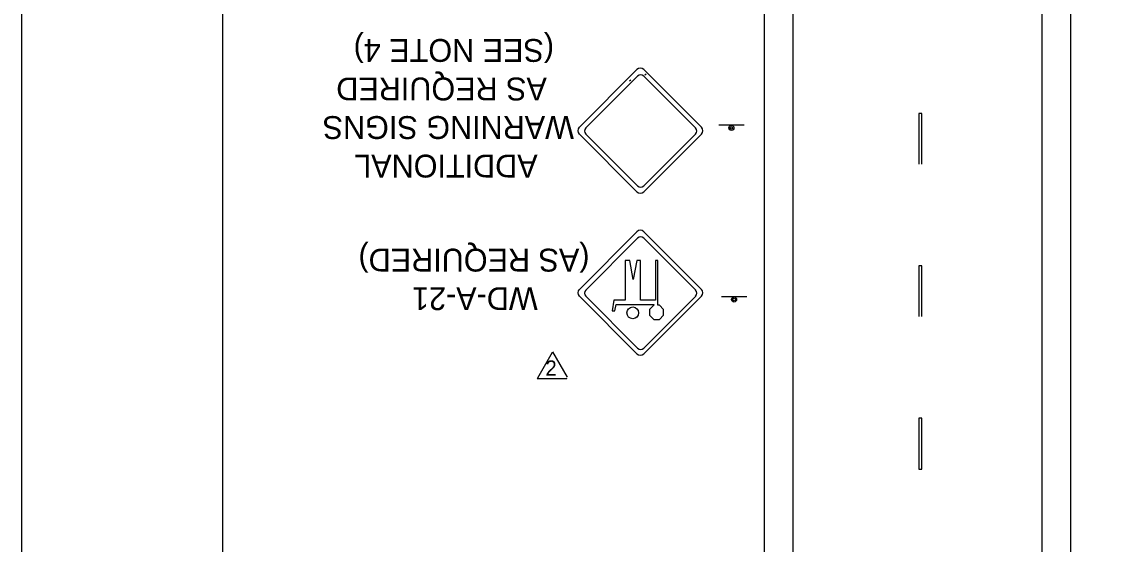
# Model space of a CAD drawing. Extents: x 2195 to 2411, y 202 to 481.
# Drawn here: x 2195.4 to 2299.6, y 363.1 to 412.8 of the extents above; entities that cross this region are included whole.
import ezdxf

# ---------------------------------------------------------------- set-up
doc = ezdxf.new("R2010")
doc.units = 0
for name, color, linetype in [('Level 1', 7, 'Continuous'), ('Level 10', 7, 'Continuous'), ('Level 2', 7, 'Continuous'), ('Level 44', 7, 'Continuous'), ('Level 60', 7, 'Continuous')]:
    doc.layers.add(name, color=color, linetype=linetype)

msp = doc.modelspace()

# ---------------------------------------------------------------- linework, layer by layer
at = {"layer": 'Level 1'}
for p, q in [((2253.3, 390.08), (2252.84, 390.08)), ((2252.84, 390.08), (2252.84, 386.29)), ((2253.62, 388.26), (2253.3, 390.08)), ((2253.96, 390.08), (2253.62, 388.26)), ((2254.33, 390.08), (2253.96, 390.08)), ((2254.33, 386.29), (2254.33, 390.08)), ((2255.95, 390.08), (2255.75, 390.08)), ((2255.75, 390.08), (2255.75, 386.29)), ((2255.95, 385.82), (2255.95, 390.08)), ((2251.77, 386.29), (2251.61, 385.29)), ((2252.84, 386.29), (2251.77, 386.29)), ((2251.86, 385.29), (2252, 385.89)), ((2252, 385.89), (2255.57, 385.89)), ((2255.75, 386.29), (2254.33, 386.29)), ((2255.57, 385.82), (2255.18, 385.42)), ((2255.57, 385.89), (2255.57, 385.82)), ((2256.13, 385.82), (2255.95, 385.82)), ((2256.52, 385.42), (2256.13, 385.82)), ((2251.61, 385.29), (2251.86, 385.29)), ((2255.18, 385.42), (2255.18, 384.86)), ((2255.18, 384.86), (2255.57, 384.47)), ((2256.13, 384.47), (2256.52, 384.86)), ((2256.52, 384.86), (2256.52, 385.42)), ((2255.57, 384.47), (2256.13, 384.47))]:
    msp.add_line(p, q, dxfattribs=at)
msp.add_circle((2253.58, 385.09), 0.559, dxfattribs=at)
at = {"layer": 'Level 10'}
for p, q in [((2266.09, 465.71), (2266.09, 217.7)), ((2268.81, 465.71), (2268.81, 217.7)), ((2292.52, 447.88), (2292.52, 311.49)), ((2295.26, 447.88), (2295.26, 217.7))]:
    msp.add_line(p, q, dxfattribs=at)
at = {"layer": 'Level 2'}
for p, q in [((2254.74, 407.74), (2254.84, 407.84)), ((2253.28, 407.17), (2253.38, 407.27)), ((2280.81, 404.08), (2280.81, 399.24)), ((2281.1, 404.08), (2280.81, 404.08)), ((2281.1, 399.24), (2281.1, 404.08)), ((2280.81, 389.57), (2280.81, 384.73)), ((2281.1, 389.57), (2280.81, 389.57)), ((2281.1, 384.73), (2281.1, 389.57)), ((2280.81, 375.05), (2280.81, 370.21)), ((2281.1, 375.05), (2280.81, 375.05)), ((2281.1, 370.21), (2281.1, 375.05)), ((2280.81, 370.21), (2281.1, 370.21))]:
    msp.add_line(p, q, dxfattribs=at)
at = {"layer": 'Level 44'}
for p, q in [((2253.97, 408.25), (2248.49, 402.75)), ((2249.1, 402.69), (2254.04, 407.63)), ((2260.11, 402.75), (2254.62, 408.25)), ((2254.62, 407.63), (2259.56, 402.69)), ((2260.11, 402.75), (2260.11, 402.75)), ((2264.18, 402.96), (2261.76, 402.96)), ((2248.49, 402.1), (2253.97, 396.62)), ((2254.04, 397.17), (2249.1, 402.11)), ((2259.56, 402.11), (2254.62, 397.17)), ((2254.62, 396.62), (2260.11, 402.1)), ((2253.98, 392.81), (2248.49, 387.32)), ((2249.1, 387.26), (2254.04, 392.2)), ((2260.12, 387.32), (2254.63, 392.81)), ((2254.63, 392.2), (2259.57, 387.26)), ((2248.49, 386.67), (2253.98, 381.19)), ((2254.04, 381.74), (2249.1, 386.68)), ((2259.57, 386.68), (2254.63, 381.74)), ((2254.63, 381.19), (2260.12, 386.67)), ((2260.11, 387.32), (2260.12, 387.32)), ((2264.45, 386.63), (2262.03, 386.63))]:
    msp.add_line(p, q, dxfattribs=at)
for centre, radius in [((2262.97, 402.69), 0.242), ((2262.97, 402.69), 0.121), ((2263.23, 386.36), 0.242), ((2263.23, 386.36), 0.121)]:
    msp.add_circle(centre, radius, dxfattribs=at)
for centre, radius, start, end in [((2254.3, 407.92), 0.459, 45, 135), ((2254.33, 407.34), 0.413, 45, 135), ((2248.81, 402.43), 0.459, 135, 225), ((2249.39, 402.4), 0.413, 135, 225), ((2259.27, 402.4), 0.413, 315, 45), ((2259.79, 402.43), 0.459, 315, 45), ((2254.33, 397.46), 0.413, 225, 315), ((2254.3, 396.94), 0.459, 225, 315), ((2254.3, 392.49), 0.459, 45, 135), ((2254.33, 391.91), 0.413, 45, 135), ((2248.81, 387), 0.459, 135, 225), ((2249.4, 386.97), 0.413, 135, 225), ((2259.27, 386.97), 0.413, 315, 45), ((2259.79, 387), 0.459, 315, 45), ((2254.33, 382.03), 0.413, 225, 315), ((2254.3, 381.51), 0.459, 225, 315)]:
    msp.add_arc(centre, radius, start, end, dxfattribs=at)
at = {"layer": 'Level 60'}
for points in [[(2195.4, 480.88), (2411.4, 480.88), (2411.4, 201.88), (2195.4, 201.88)], [(2214.53, 470.07), (2401.4, 470.07), (2401.4, 212.69), (2214.53, 212.69)]]:
    msp.add_lwpolyline(points, close=True, dxfattribs=at)
for points in [[(2245.89, 381.31), (2244.5, 378.88)], [(2247.37, 378.96), (2245.98, 381.38)], [(2244.5, 378.88), (2244.47, 378.84), (2247.31, 378.84), (2247.29, 378.88)]]:
    msp.add_lwpolyline(points, dxfattribs=at)

# ---------------------------------------------------------------- texts
at = {"layer": 'Level 10'}
for s, height, p in [('(SEE NOTE 4)', 2.177, (2246.08, 411.16)), ('AS REQUIRED', 2.177, (2245.4, 407.49)), ('WARNING SIGNS ', 2.177, (2247.98, 403.82)), ('ADDITIONAL ', 2.177, (2244.52, 400.15)), ('(AS REQUIRED)', 2.1779, (2249.46, 391.2)), ('WD-A-21', 2.178, (2244.53, 387.53))]:
    msp.add_text(s, height=height, rotation=180, dxfattribs=at).set_placement(p)
at = {"layer": 'Level 60'}
msp.add_text('2', height=1.45, rotation=360, dxfattribs=at).set_placement((2245.26, 379.11))

doc.saveas('drawing.dxf')
